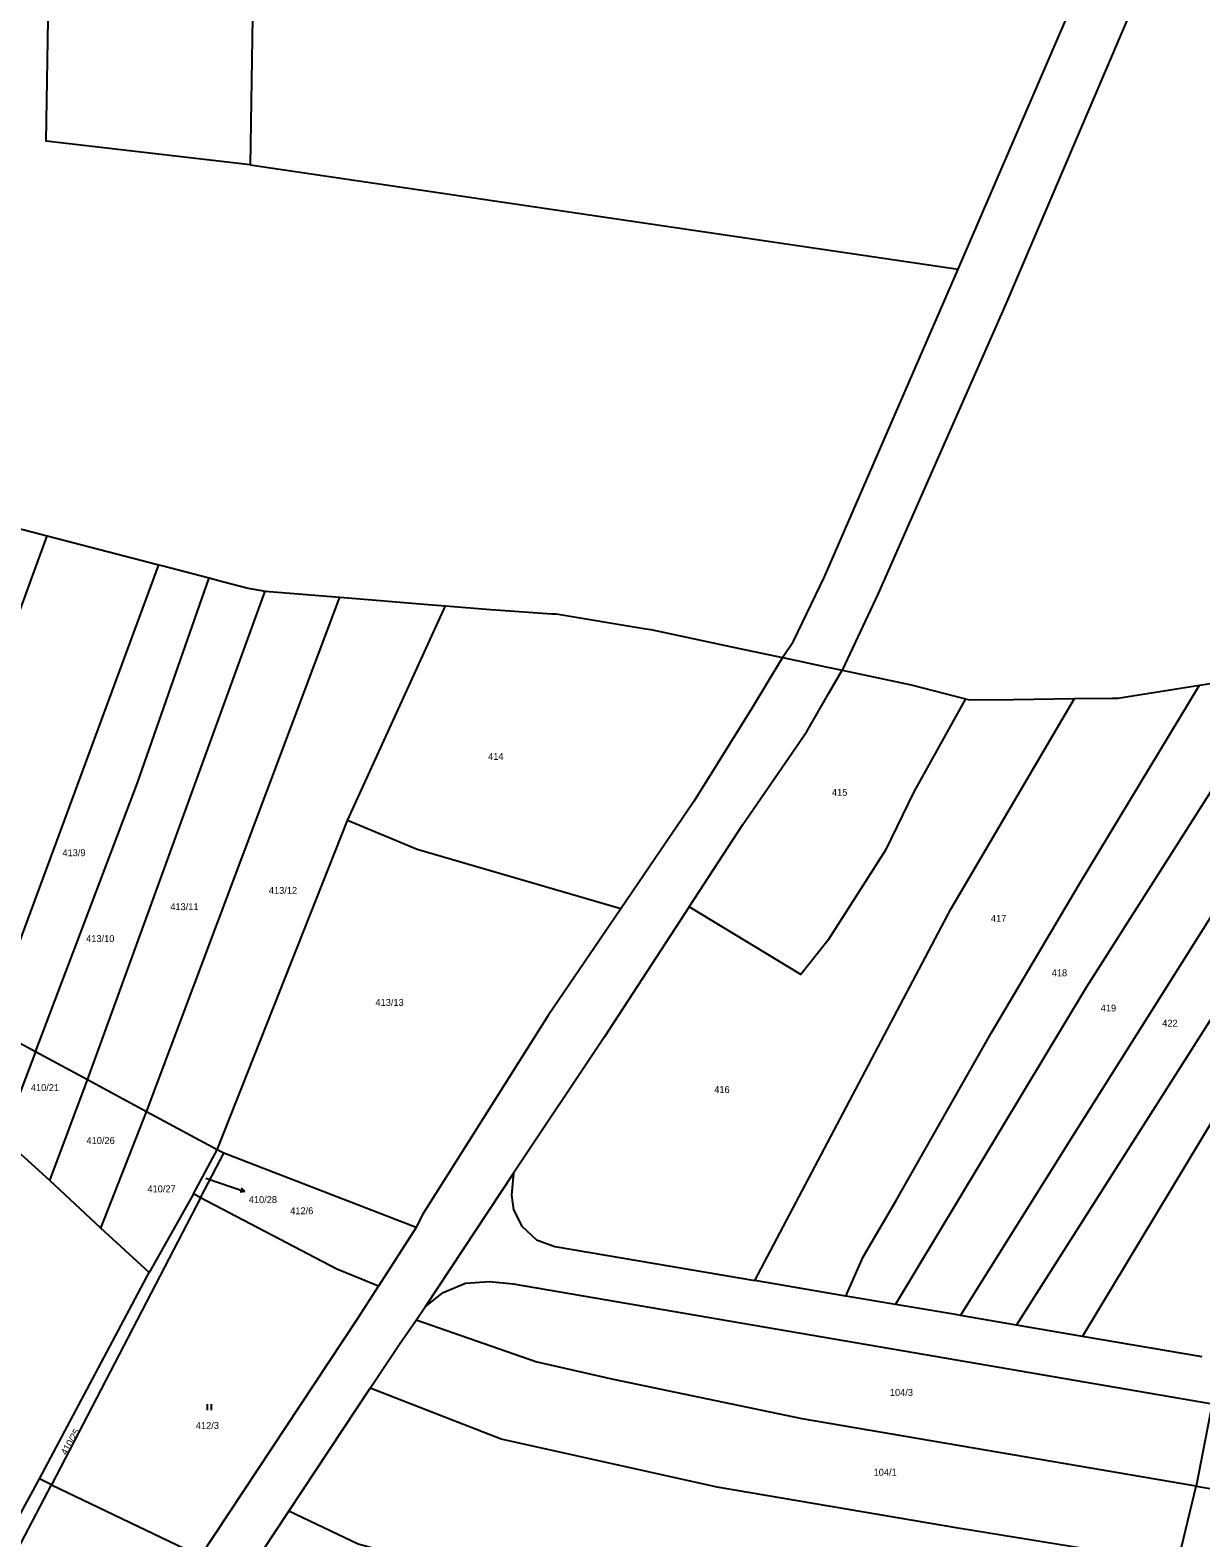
# Model space of a CAD drawing. Extents: x -746176 to -739709, y -1128407 to -1124482.
# Drawn here: x -743602.7 to -743314.3, y -1127113.6 to -1126742.1 of the extents above; entities that cross this region are included whole.
import ezdxf

# ---------------------------------------------------------------- set-up
doc = ezdxf.new("R2010")
doc.units = 0
for name, color, linetype in [('Hranice parcel', 7, 'Continuous'), ('Parcelní čísla', 7, 'Continuous'), ('Pop  PČ popisy', 7, 'Continuous'), ('Značky kultur', 7, 'Continuous')]:
    doc.layers.add(name, color=color, linetype=linetype)

msp = doc.modelspace()

# ---------------------------------------------------------------- linework, layer by layer
at = {"layer": 'Hranice parcel'}
for p, q in [((-743546.06, -1126620.02), (-743548.45, -1126775.3)), ((-743374.08, -1126801), (-743346.47, -1126737.09)), ((-743548.45, -1126775.3), (-743374.08, -1126801)), ((-743613.43, -1126862.82), (-743598.46, -1126866.7)), ((-743613.43, -1126862.82), (-743598.46, -1126866.7)), ((-743637.84, -1126974.2), (-743598.46, -1126866.7)), ((-743598.46, -1126866.7), (-743570.98, -1126873.86)), ((-743598.46, -1126866.7), (-743570.98, -1126873.86)), ((-743588.59, -1127000.75), (-743544.8, -1126880.33)), ((-743558.58, -1126877.09), (-743555.26, -1126877.96)), ((-743558.58, -1126877.09), (-743555.26, -1126877.96)), ((-743555.26, -1126877.96), (-743548.99, -1126879.59)), ((-743555.26, -1126877.96), (-743548.99, -1126879.59)), ((-743548.99, -1126879.59), (-743544.8, -1126880.33)), ((-743548.99, -1126879.59), (-743544.8, -1126880.33)), ((-743573.98, -1127008.62), (-743526.35, -1126881.85)), ((-743524.49, -1126936.89), (-743500.35, -1126883.98)), ((-743556.57, -1127018), (-743524.49, -1126936.89)), ((-743601.38, -1126993.85), (-743613.12, -1126987.52)), ((-743601.38, -1126993.85), (-743609.42, -1127015.07)), ((-743588.59, -1127000.75), (-743601.38, -1126993.85)), ((-743597.86, -1127025.57), (-743588.59, -1127000.75)), ((-743573.98, -1127008.62), (-743588.59, -1127000.75)), ((-743585.23, -1127037.3), (-743573.98, -1127008.62)), ((-743556.57, -1127018), (-743573.98, -1127008.62)), ((-743597.86, -1127025.57), (-743609.42, -1127015.07)), ((-743562.48, -1127028.88), (-743556.57, -1127018)), ((-743560.68, -1127029.82), (-743554.98, -1127018.86)), ((-743554.98, -1127018.86), (-743556.57, -1127018)), ((-743507.61, -1127037.13), (-743554.98, -1127018.86)), ((-743483.62, -1127023.79), (-743505.37, -1127056.75)), ((-743585.23, -1127037.3), (-743597.86, -1127025.57)), ((-743562.48, -1127028.88), (-743573.39, -1127048.24)), ((-743560.68, -1127029.82), (-743562.48, -1127028.88)), ((-743560.68, -1127029.82), (-743597.45, -1127100.54)), ((-743573.39, -1127048.24), (-743585.23, -1127037.3)), ((-743507.61, -1127037.13), (-743516.89, -1127051.64)), ((-743600.41, -1127099.12), (-743573.39, -1127048.24)), ((-743401.72, -1127054.05), (-743424.12, -1127050.25)), ((-743389.47, -1127056.13), (-743401.72, -1127054.05)), ((-743507.61, -1127059.97), (-743505.37, -1127056.75)), ((-743359.71, -1127061.21), (-743373.46, -1127058.85)), ((-743343.4, -1127064.01), (-743359.71, -1127061.21)), ((-743313.92, -1127069.06), (-743343.4, -1127064.01)), ((-743538.97, -1127107.07), (-743518.91, -1127076.75)), ((-743311.47, -1127080.65), (-743315.45, -1127100.94)), ((-743646.48, -1127183.8), (-743600.41, -1127099.12)), ((-743597.45, -1127100.54), (-743600.41, -1127099.12)), ((-743642.12, -1127186.45), (-743597.45, -1127100.54)), ((-743597.45, -1127100.54), (-743560.72, -1127118.19)), ((-743320.04, -1127120.06), (-743315.45, -1127100.94)), ((-743549.04, -1127122.29), (-743538.97, -1127107.07))]:
    msp.add_line(p, q, dxfattribs=at)
for points in [[(-743548.45, -1126775.3), (-743598.7, -1126769.47), (-743596.48, -1126634.64)], [(-743305.53, -1126676.38), (-743362.58, -1126810.12), (-743393.73, -1126880.97), (-743402.66, -1126899.83)], [(-743417.33, -1126896.72), (-743414.66, -1126892.7), (-743406.95, -1126876.81), (-743374.08, -1126801)], [(-743613.12, -1126987.52), (-743604.54, -1126964.89), (-743570.98, -1126873.86)], [(-743570.98, -1126873.86), (-743570.28, -1126874.05), (-743558.58, -1126877.09)], [(-743570.98, -1126873.86), (-743570.28, -1126874.05), (-743558.58, -1126877.09)], [(-743601.38, -1126993.85), (-743576.26, -1126927.6), (-743558.58, -1126877.09)], [(-743544.8, -1126880.33), (-743529.54, -1126881.59), (-743526.35, -1126881.85)], [(-743544.8, -1126880.33), (-743529.54, -1126881.59), (-743526.35, -1126881.85)], [(-743526.35, -1126881.85), (-743516.49, -1126882.66), (-743504.64, -1126883.63), (-743500.35, -1126883.98)], [(-743526.35, -1126881.85), (-743516.49, -1126882.66), (-743504.64, -1126883.63), (-743500.35, -1126883.98)], [(-743500.35, -1126883.98), (-743489.25, -1126884.88), (-743487.94, -1126884.99), (-743474.2, -1126885.91), (-743473.08, -1126885.98), (-743451, -1126889.6), (-743449.81, -1126889.8), (-743427.91, -1126894.47), (-743417.33, -1126896.72)], [(-743500.35, -1126883.98), (-743489.25, -1126884.88), (-743487.94, -1126884.99), (-743474.2, -1126885.91), (-743473.08, -1126885.98), (-743451, -1126889.6), (-743449.81, -1126889.8), (-743427.91, -1126894.47), (-743417.33, -1126896.72)], [(-743359.71, -1127061.21), (-743292.37, -1126955.23), (-743255.64, -1126895.06)], [(-743343.4, -1127064.01), (-743303.47, -1126997.62), (-743275.93, -1126953.86), (-743239.29, -1126892.07)], [(-743417.33, -1126896.72), (-743424.78, -1126909.13), (-743439.2, -1126932.19), (-743457.17, -1126958.62)], [(-743417.33, -1126896.72), (-743413.79, -1126897.47), (-743406.62, -1126898.99), (-743402.66, -1126899.83)], [(-743417.33, -1126896.72), (-743413.79, -1126897.47), (-743406.62, -1126898.99), (-743402.66, -1126899.83)], [(-743373.46, -1127058.85), (-743345.29, -1127013.85), (-743271.77, -1126897.03)], [(-743440.35, -1126958.18), (-743427.08, -1126937.82), (-743411.38, -1126914.91), (-743405.93, -1126905.47), (-743402.66, -1126899.83)], [(-743402.66, -1126899.83), (-743385.6, -1126903.46), (-743372.24, -1126906.89)], [(-743402.66, -1126899.83), (-743385.6, -1126903.46), (-743372.24, -1126906.89)], [(-743389.47, -1127056.13), (-743342.45, -1126977.97), (-743292.9, -1126900.09)], [(-743314.63, -1126903.54), (-743307.33, -1126902.38), (-743292.9, -1126900.09)], [(-743314.63, -1126903.54), (-743307.33, -1126902.38), (-743292.9, -1126900.09)], [(-743401.72, -1127054.05), (-743397.47, -1127044.4), (-743389.37, -1127030.54), (-743365.92, -1126989.29), (-743344.18, -1126952.46), (-743314.63, -1126903.54)], [(-743345.39, -1126906.84), (-743336.16, -1126906.74), (-743334.69, -1126906.72), (-743314.63, -1126903.54)], [(-743345.39, -1126906.84), (-743336.16, -1126906.74), (-743334.69, -1126906.72), (-743314.63, -1126903.54)], [(-743372.24, -1126906.89), (-743384.97, -1126929.79), (-743392, -1126944.18), (-743406.19, -1126966.46), (-743412.83, -1126974.8), (-743440.35, -1126958.18)], [(-743424.12, -1127050.25), (-743375.85, -1126958.71), (-743345.39, -1126906.84)], [(-743372.24, -1126906.89), (-743371.28, -1126907.14), (-743360.4, -1126907.02), (-743345.39, -1126906.84)], [(-743372.24, -1126906.89), (-743371.28, -1126907.14), (-743360.4, -1126907.02), (-743345.39, -1126906.84)], [(-743457.17, -1126958.62), (-743507.35, -1126943.98), (-743524.49, -1126936.89)], [(-743440.35, -1126958.18), (-743461.19, -1126990.18), (-743483.62, -1127023.79)], [(-743457.17, -1126958.62), (-743475.03, -1126984.89), (-743506.07, -1127034.13), (-743507.61, -1127037.13)], [(-743483.62, -1127023.79), (-743484.09, -1127029.22), (-743483.64, -1127032.8), (-743481.55, -1127036.83), (-743477.98, -1127040.17), (-743473.44, -1127041.87), (-743424.12, -1127050.25)], [(-743516.89, -1127051.64), (-743527.15, -1127047.39), (-743560.68, -1127029.82)], [(-743505.37, -1127056.75), (-743500.91, -1127053.2), (-743495.43, -1127050.9), (-743489.52, -1127050.44), (-743483.7, -1127051.01), (-743385.04, -1127067.93), (-743311.47, -1127080.65)], [(-743560.72, -1127118.19), (-743522.03, -1127059.68), (-743516.89, -1127051.64)], [(-743373.46, -1127058.85), (-743374.75, -1127058.63), (-743389.47, -1127056.13)], [(-743518.91, -1127076.75), (-743511.71, -1127065.87), (-743507.61, -1127059.97)], [(-743315.45, -1127100.94), (-743412.49, -1127084.27), (-743458.97, -1127074.63), (-743478.13, -1127070.26), (-743507.61, -1127059.97)], [(-743320.04, -1127120.06), (-743373.57, -1127111.3), (-743433.39, -1127101.15), (-743486.65, -1127089.31), (-743518.91, -1127076.75)], [(-743315.45, -1127100.94), (-743241.34, -1127113.11), (-743196.1, -1127119.89)], [(-743227.63, -1127169.97), (-743272.53, -1127161.95), (-743339.46, -1127150.28), (-743422.36, -1127136.74), (-743485.93, -1127125.07), (-743521.87, -1127115.17), (-743538.97, -1127107.07)]]:
    msp.add_lwpolyline(points, dxfattribs=at)
at = {"layer": 'Pop  PČ popisy'}
for p, q in [((-743559.41, -1127025), (-743552.66, -1127027.33)), ((-743552.66, -1127027.33), (-743549.82, -1127028.31)), ((-743549.82, -1127028.31), (-743550.93, -1127028.45)), ((-743549.82, -1127028.31), (-743550.61, -1127027.51))]:
    msp.add_line(p, q, dxfattribs=at)
at = {"layer": 'Značky kultur'}
for p, q in [((-743559, -1127082.18), (-743559, -1127080.68)), ((-743558, -1127082.18), (-743558, -1127080.68))]:
    msp.add_line(p, q, dxfattribs=at)

# ---------------------------------------------------------------- texts
at = {"layer": 'Parcelní čísla'}
for s, p in [('414', (-743489.84, -1126921.93)), ('415', (-743405.15, -1126930.78)), ('413/9', (-743594.73, -1126945.66)), ('413/12', (-743543.87, -1126954.94)), ('413/11', (-743568.15, -1126958.96)), ('417', (-743365.99, -1126961.84)), ('413/10', (-743588.89, -1126966.82)), ('418', (-743351.01, -1126975.26)), ('413/13', (-743517.6, -1126982.54)), ('419', (-743338.93, -1126983.93)), ('422', (-743323.78, -1126987.67)), ('410/21', (-743602.51, -1127003.54)), ('416', (-743434.15, -1127004.02)), ('410/26', (-743588.8, -1127016.57)), ('410/27', (-743573.79, -1127028.49)), ('410/28', (-743548.82, -1127031.14)), ('412/6', (-743538.61, -1127033.89)), ('104/3', (-743390.88, -1127078.65)), ('412/3', (-743561.86, -1127086.8)), ('104/1', (-743394.9, -1127098.32))]:
    msp.add_text(s, height=1.7, dxfattribs=at).set_placement(p)
msp.add_text('410/25', height=1.7, rotation=60, dxfattribs=at).set_placement((-743593.76, -1127093.4))

doc.saveas('drawing.dxf')
